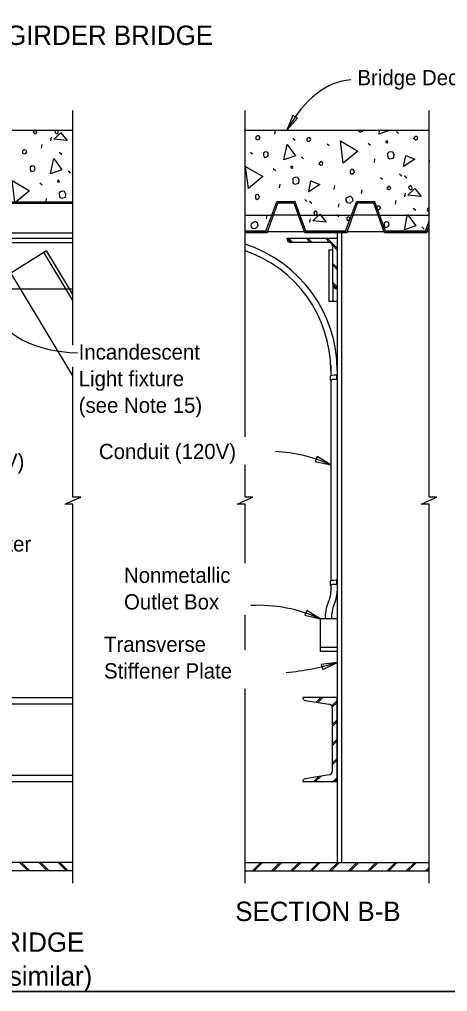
# Model space of a CAD drawing. Extents: x 0 to 30.8, y 0 to 21.2.
# Drawn here: x 8.22 to 12.47, y 0 to 9.63 of the extents above; entities that cross this region are included whole.
import ezdxf

# ---------------------------------------------------------------- set-up
doc = ezdxf.new("R2010")
doc.units = 0
for name, color, linetype in [('ActivePts-ConstElements', 7, 'Continuous'), ('Dimension', 7, 'Continuous'), ('Lighting', 7, 'Continuous'), ('Miscellaneous', 7, 'Continuous'), ('Miscellaneous1', 7, 'Continuous'), ('SteelGirder', 7, 'Continuous'), ('SteelGirder_h', 7, 'Continuous'), ('SupstrConc', 7, 'Continuous'), ('TextStructures', 7, 'Continuous')]:
    doc.layers.add(name, color=color, linetype=linetype)

msp = doc.modelspace()

# ---------------------------------------------------------------- linework, layer by layer
at = {"layer": 'ActivePts-ConstElements'}
msp.add_lwpolyline([(0, 0), (30.7879, 0), (30.7879, 19.4596), (0, 19.4596)], close=True, dxfattribs=at)
at = {"layer": 'Dimension'}
for points in [[(8.7519, 6.4065), (8.7519, 8.7314)], [(10.4598, 5.4959), (10.4598, 8.7314)], [(12.2847, 1.0713), (12.2847, 4.831), (12.2072, 4.831), (12.2847, 4.8647), (12.3622, 4.8985), (12.2847, 4.8985), (12.2847, 8.7314)], [(8.7519, 1.0713), (8.7519, 4.831), (8.6744, 4.831), (8.7519, 4.8647), (8.8294, 4.8985), (8.7519, 4.8985), (8.7519, 6.1908)], [(10.4598, 4.244), (10.4598, 4.831), (10.3823, 4.831), (10.4598, 4.8647), (10.5373, 4.8985), (10.4598, 4.8985), (10.4598, 5.2178)], [(10.4598, 3.3853), (10.4598, 3.7314)], [(10.4598, 1.0713), (10.4598, 2.9979)]]:
    msp.add_lwpolyline(points, dxfattribs=at)
for points in [[(10.8735, 8.5353), (10.9781, 8.6542), (10.9331, 8.682)], [(11.31, 5.2178), (11.176, 5.3023), (11.1557, 5.2534)], [(11.2058, 3.6925), (11.0718, 3.777), (11.0514, 3.7281)], [(11.3725, 3.2613), (11.2156, 3.2395), (11.2315, 3.189)]]:
    msp.add_lwpolyline(points, close=True, dxfattribs=at)
for centre, radius, start, end in [((10.6912, 3.8596), 1.4925, 65.50737, 87.36586), ((10.587, 2.3343), 1.4925, 65.50737, 92.69977), ((10.6816, 5.4517), 2.2968, 274.66721, 287.50633)]:
    msp.add_arc(centre, radius, start, end, dxfattribs=at)
for centre, major_axis, ratio, start_param, end_param in [((11.6186, 6.6665), (0.1111, -2.3674), 0.464296, 3.141604, 3.781059), ((9.2695, 7.2066), (1.3013, 0.4369), 0.58496, 3.141593, 4.152777)]:
    msp.add_ellipse(centre, major_axis=major_axis, ratio=ratio, start_param=start_param, end_param=end_param, dxfattribs=at)
at = {"layer": 'Lighting'}
for p, q in [((11.31, 6.2072), (11.31, 6.1026)), ((11.31, 6.059), (11.31, 4.0705)), ((11.31, 4.0268), (11.31, 3.9651)), ((11.3725, 3.6925), (11.2058, 3.6925)), ((11.2058, 3.6925), (11.2058, 3.3691)), ((11.2579, 3.6925), (11.2579, 3.7429)), ((11.3204, 3.6925), (11.3204, 3.7429)), ((11.3725, 3.4095), (11.2058, 3.4095)), ((11.3725, 3.3691), (11.2058, 3.3691))]:
    msp.add_line(p, q, dxfattribs=at)
for centre, radius, start, end in [((10.06, 6.1551), 1.3125, 0.00119, 72.26682), ((10.06, 6.1551), 1.25, 0, 71.34833), ((11.06, 3.9651), 0.25, 333.61151, 0), ((11.06, 3.9651), 0.3125, 333.61151, 0.00004), ((11.5079, 3.7429), 0.25, 153.61151, 179.99999), ((11.5079, 3.7429), 0.1875, 153.61151, 179.99999)]:
    msp.add_arc(centre, radius, start, end, dxfattribs=at)
at = {"layer": 'Miscellaneous'}
for p, q in [((10.7561, 8.4962), (10.7616, 8.5339)), ((11.96, 8.5237), (11.981, 8.5034)), ((8.4407, 8.3567), (8.4461, 8.3944)), ((8.5323, 8.4304), (8.5383, 8.4657)), ((10.932, 8.4579), (10.9578, 8.4389)), ((11.2732, 8.4018), (11.2935, 8.3839)), ((11.6806, 8.4074), (11.704, 8.3878)), ((8.6166, 8.3184), (8.6424, 8.2994)), ((10.5141, 8.3175), (10.5338, 8.302)), ((11.0183, 8.2714), (11.0392, 8.2511)), ((11.742, 8.2168), (11.7481, 8.2521)), ((12.2844, 8.2017), (12.2899, 8.2394)), ((8.7028, 8.1319), (8.7238, 8.1116)), ((10.7388, 8.1551), (10.7622, 8.1355)), ((11.9926, 8.1028), (12.0135, 8.0825)), ((8.4234, 8.0156), (8.4468, 7.996)), ((10.8003, 7.9645), (10.8063, 7.9998)), ((11.8028, 8.0675), (11.8231, 8.0496)), ((12.0414, 8.0848), (12.0624, 8.0646)), ((11.3427, 7.9494), (11.3481, 7.987)), ((11.615, 7.9085), (11.6204, 7.9461)), ((12.0431, 7.8756), (12.0492, 7.9109)), ((3.9317, 7.827), (8.7519, 7.827)), ((3.9359, 7.8114), (8.7519, 7.8114)), ((8.4852, 7.827), (8.4909, 7.8603)), ((10.6666, 7.5353), (10.7728, 7.827)), ((10.6775, 7.5197), (10.7837, 7.8114)), ((10.9561, 7.827), (10.7728, 7.827)), ((10.9452, 7.8114), (10.7837, 7.8114)), ((11.0514, 7.5197), (10.9452, 7.8114)), ((11.0623, 7.5353), (10.9561, 7.827)), ((11.0508, 7.8504), (11.0718, 7.8302)), ((11.0996, 7.8325), (11.1206, 7.8122)), ((11.3851, 7.7718), (11.3911, 7.8071)), ((11.457, 7.5353), (11.5632, 7.827)), ((11.468, 7.5197), (11.5742, 7.8114)), ((11.7465, 7.827), (11.5632, 7.827)), ((11.7356, 7.8114), (11.5742, 7.8114)), ((11.8418, 7.5197), (11.7356, 7.8114)), ((11.8527, 7.5353), (11.7465, 7.827)), ((11.9516, 7.8019), (11.957, 7.8396)), ((12.1275, 7.7636), (12.1532, 7.7447)), ((10.6732, 7.6561), (10.6787, 7.6938)), ((11.1013, 7.6233), (11.1074, 7.6586)), ((11.365, 7.7017), (11.3884, 7.6821)), ((12.2475, 7.5353), (12.2847, 7.6375)), ((3.2598, 7.5197), (8.7519, 7.5197)), ((10.6666, 7.5353), (10.4598, 7.5353)), ((10.6775, 7.5197), (10.4598, 7.5197)), ((11.468, 7.5197), (11.0514, 7.5197)), ((11.457, 7.5353), (11.0623, 7.5353)), ((12.2584, 7.5197), (11.8418, 7.5197)), ((12.2475, 7.5353), (11.8527, 7.5353)), ((12.2137, 7.5771), (12.2346, 7.5568)), ((12.2584, 7.5197), (12.2847, 7.5919)), ((10.9154, 7.4231), (10.8737, 7.4648)), ((10.9331, 7.4231), (10.8914, 7.4648)), ((11.1063, 7.4231), (11.0647, 7.4648)), ((11.124, 7.4231), (11.0823, 7.4648)), ((11.2997, 7.4207), (11.2556, 7.4648)), ((11.3725, 7.3655), (11.2732, 7.4648)), ((11.3725, 7.3478), (11.3282, 7.3921)), ((11.3725, 7.1746), (11.3308, 7.2162)), ((11.3725, 7.1569), (11.3308, 7.1986)), ((11.3725, 6.9837), (11.3308, 7.0253)), ((11.3725, 6.966), (11.3308, 7.0076)), ((11.0326, 2.907), (11.0382, 2.9127)), ((11.1652, 2.8664), (11.2115, 2.9127)), ((11.1804, 2.8639), (11.2291, 2.9127)), ((11.3178, 2.828), (11.3725, 2.8828)), ((11.3232, 2.8158), (11.3725, 2.8651)), ((11.3246, 2.644), (11.3725, 2.6919)), ((11.3246, 2.6263), (11.3725, 2.6742)), ((11.3246, 2.453), (11.3725, 2.5009)), ((11.3246, 2.4354), (11.3725, 2.4833)), ((11.3246, 2.2621), (11.3725, 2.31)), ((11.3246, 2.2444), (11.3725, 2.2924)), ((11.1418, 2.0793), (11.1925, 2.1301)), ((11.1595, 2.0793), (11.2137, 2.1335)), ((11.3327, 2.0793), (11.3725, 2.1191)), ((11.3504, 2.0793), (11.3725, 2.1014)), ((8.3064, 1.1941), (8.2231, 1.2774)), ((8.3241, 1.1941), (8.2408, 1.2774)), ((8.4973, 1.1941), (8.414, 1.2774)), ((8.515, 1.1941), (8.4317, 1.2774)), ((8.6882, 1.1941), (8.605, 1.2774)), ((8.7059, 1.1941), (8.6226, 1.2774)), ((10.5314, 1.1941), (10.6147, 1.2774)), ((10.5491, 1.1941), (10.6324, 1.2774)), ((10.7223, 1.1941), (10.8056, 1.2774)), ((10.74, 1.1941), (10.8233, 1.2774)), ((10.9133, 1.1941), (10.9965, 1.2774)), ((10.9309, 1.1941), (11.0142, 1.2774)), ((11.1042, 1.1941), (11.1875, 1.2774)), ((11.1219, 1.1941), (11.2051, 1.2774)), ((11.2951, 1.1941), (11.3784, 1.2774)), ((11.3128, 1.1941), (11.3961, 1.2774)), ((11.486, 1.1941), (11.5693, 1.2774)), ((11.5037, 1.1941), (11.587, 1.2774)), ((11.6769, 1.1941), (11.7602, 1.2774)), ((11.6946, 1.1941), (11.7779, 1.2774)), ((11.8679, 1.1941), (11.9511, 1.2774)), ((11.8855, 1.1941), (11.9688, 1.2774)), ((12.0588, 1.1941), (12.1421, 1.2774)), ((12.0765, 1.1941), (12.1597, 1.2774)), ((12.2497, 1.1941), (12.2847, 1.2291)), ((12.2674, 1.1941), (12.2847, 1.2114))]:
    msp.add_line(p, q, dxfattribs=at)
for points in [[(8.3561, 8.5178), (8.3703, 8.5035), (8.3855, 8.5049), (8.3932, 8.5148), (8.3919, 8.5196), (8.3832, 8.5328), (8.3768, 8.5353)], [(8.3699, 8.5353), (8.3638, 8.5276), (8.3561, 8.5178)], [(8.5617, 8.446), (8.6322, 8.5115), (8.6947, 8.4325), (8.5617, 8.446)], [(8.5821, 8.5353), (8.5796, 8.5337), (8.5713, 8.5263), (8.5752, 8.5118)], [(8.5752, 8.5118), (8.585, 8.504), (8.5984, 8.5025), (8.6067, 8.5099), (8.6065, 8.5202), (8.6009, 8.5316), (8.5981, 8.5353)], [(10.5674, 8.4663), (10.5671, 8.4481), (10.5849, 8.4399), (10.5987, 8.4462), (10.61, 8.4622), (10.6019, 8.473), (10.5951, 8.4789), (10.5842, 8.4812), (10.5793, 8.4799), (10.5674, 8.4663)], [(11.5846, 8.5353), (11.5938, 8.5188), (11.6114, 8.5209), (11.6228, 8.5265), (11.6279, 8.5353)], [(11.7865, 8.4953), (11.795, 8.5353)], [(11.8978, 8.5353), (11.7865, 8.4953)], [(10.8447, 8.243), (10.8767, 8.3939), (10.958, 8.2837), (10.8447, 8.243)], [(11.0738, 8.4312), (11.0799, 8.4276), (11.0957, 8.4267), (11.1082, 8.4378), (11.1111, 8.4464), (11.1024, 8.4596), (11.0818, 8.4592), (11.0734, 8.4518), (11.0712, 8.4408), (11.0738, 8.4312)], [(11.4335, 8.2092), (11.4055, 8.4295), (11.5776, 8.3281), (11.4335, 8.2092)], [(11.8545, 8.4152), (11.8758, 8.4131), (11.8732, 8.4228), (11.8651, 8.4336), (11.8543, 8.4255), (11.8545, 8.4152)], [(12.1347, 8.4515), (12.1531, 8.4408), (12.1675, 8.4447), (12.1727, 8.4642), (12.1537, 8.4772), (12.1453, 8.4698), (12.1363, 8.4648), (12.1347, 8.4515), (12.1334, 8.4563)], [(8.252, 8.3268), (8.2517, 8.3086), (8.2694, 8.3004), (8.2833, 8.3067), (8.2945, 8.3227), (8.2865, 8.3335), (8.2797, 8.3394), (8.2687, 8.3417), (8.2639, 8.3404), (8.252, 8.3268)], [(10.6435, 8.3081), (10.6421, 8.2844), (10.6521, 8.2664), (10.6696, 8.2685), (10.681, 8.2742), (10.6916, 8.2926), (10.6858, 8.3143), (10.6681, 8.3225), (10.656, 8.3192), (10.6435, 8.3081)], [(11.8733, 8.3064), (11.8747, 8.2627), (11.8955, 8.2528), (11.9075, 8.256), (11.9341, 8.2631), (11.9384, 8.2953), (11.924, 8.32), (11.9052, 8.3227), (11.8859, 8.3175), (11.8733, 8.3064)], [(8.5293, 8.1035), (8.5613, 8.2544), (8.6426, 8.1442), (8.5293, 8.1035)], [(11.1929, 8.1991), (11.2113, 8.1885), (11.2258, 8.1924), (11.2309, 8.2119), (11.2119, 8.2249), (11.2035, 8.2175), (11.1945, 8.2125), (11.1929, 8.1991), (11.1916, 8.2039)], [(12.0319, 8.178), (12.055, 8.2852), (12.1423, 8.249), (12.0319, 8.178)], [(8.328, 8.1686), (8.3266, 8.1449), (8.3366, 8.1269), (8.3542, 8.129), (8.3656, 8.1347), (8.3762, 8.1531), (8.3704, 8.1748), (8.3527, 8.183), (8.3406, 8.1797), (8.328, 8.1686)], [(10.4917, 7.9569), (10.4638, 8.1771), (10.6359, 8.0757), (10.4917, 7.9569)], [(10.9127, 8.1629), (10.934, 8.1608), (10.9314, 8.1705), (10.9234, 8.1812), (10.9126, 8.1732), (10.9127, 8.1629)], [(11.5033, 8.1322), (11.503, 8.114), (11.5196, 8.1003), (11.5352, 8.1097), (11.5454, 8.1201), (11.5421, 8.1322), (11.5328, 8.1478), (11.5163, 8.1512), (11.5038, 8.1401), (11.5033, 8.1322)], [(8.1751, 7.827), (8.1483, 8.0376), (8.3204, 7.9362), (8.188, 7.827)], [(8.5973, 8.0234), (8.6186, 8.0213), (8.616, 8.031), (8.6079, 8.0417), (8.5971, 8.0337), (8.5973, 8.0234)], [(10.9316, 8.054), (10.9329, 8.0104), (10.9537, 8.0004), (10.9658, 8.0037), (10.9923, 8.0108), (10.9966, 8.043), (10.9823, 8.0676), (10.9634, 8.0703), (10.9441, 8.0651), (10.9316, 8.054)], [(11.0902, 7.9257), (11.1132, 8.0328), (11.2006, 7.9967), (11.0902, 7.9257)], [(8.6161, 7.9145), (8.6175, 7.8709), (8.6383, 7.8609), (8.6503, 7.8642), (8.6769, 7.8713), (8.6812, 7.9035), (8.6668, 7.9281), (8.648, 7.9308), (8.6287, 7.9256), (8.6161, 7.9145)], [(11.867, 7.963), (11.8812, 7.9487), (11.8963, 7.9502), (11.904, 7.96), (11.9027, 7.9648), (11.894, 7.978), (11.8824, 7.9827), (11.8747, 7.9729), (11.867, 7.963)], [(12.0726, 7.8913), (12.143, 7.9568), (12.2056, 7.8778), (12.0726, 7.8913)], [(12.086, 7.957), (12.0958, 7.9493), (12.1092, 7.9477), (12.1176, 7.9551), (12.1174, 7.9654), (12.1117, 7.9768), (12.1037, 7.9876), (12.0905, 7.9789), (12.0821, 7.9715), (12.086, 7.957)], [(10.5615, 7.8798), (10.5612, 7.8616), (10.5778, 7.8479), (10.5934, 7.8573), (10.6036, 7.8678), (10.6003, 7.8799), (10.591, 7.8955), (10.5746, 7.8988), (10.562, 7.8877), (10.5615, 7.8798)], [(11.4573, 7.8403), (11.471, 7.8181), (11.5032, 7.8138), (11.5325, 7.8398), (11.526, 7.8639), (11.5088, 7.88), (11.496, 7.8792), (11.4756, 7.8685), (11.46, 7.8592), (11.4573, 7.8403)], [(11.1442, 7.7047), (11.1541, 7.6969), (11.1674, 7.6953), (11.1758, 7.7028), (11.1756, 7.7131), (11.17, 7.7245), (11.1619, 7.7353), (11.1487, 7.7266), (11.1403, 7.7191), (11.1442, 7.7047)], [(11.7753, 7.748), (11.7803, 7.7457), (11.7941, 7.752), (11.8054, 7.7679), (11.7973, 7.7787), (11.7905, 7.7847), (11.7796, 7.7869), (11.7748, 7.7856), (11.7655, 7.775)], [(12.2847, 7.7651), (12.2772, 7.765), (12.2689, 7.7575), (12.2666, 7.7466), (12.2692, 7.7369)], [(12.2692, 7.7369), (12.2753, 7.7334), (12.2847, 7.7328)], [(10.5155, 7.588), (10.5292, 7.5658), (10.5614, 7.5614), (10.5907, 7.5874), (10.5842, 7.6116), (10.567, 7.6276), (10.5543, 7.6268), (10.5338, 7.6162), (10.5182, 7.6068), (10.5155, 7.588)], [(11.1308, 7.6389), (11.2012, 7.7044), (11.2638, 7.6254), (11.1308, 7.6389)], [(11.4676, 7.6567), (11.4715, 7.6422), (11.4843, 7.6431), (11.4957, 7.6487), (11.5015, 7.6658), (11.4947, 7.6717), (11.4831, 7.6764), (11.4686, 7.6725), (11.4676, 7.6567)], [(11.8389, 7.6139), (11.8375, 7.5902), (11.8475, 7.5722), (11.865, 7.5743), (11.8765, 7.5799), (11.8871, 7.5983), (11.8812, 7.62), (11.8635, 7.6282), (11.8514, 7.625), (11.8389, 7.6139)], [(12.0401, 7.5487), (12.0721, 7.6996), (12.1534, 7.5894), (12.0401, 7.5487)]]:
    msp.add_lwpolyline(points, dxfattribs=at)
at = {"layer": 'Miscellaneous1'}
msp.add_lwpolyline([(0, 19.8), (30.8, 19.8), (30.8, 0), (0, 0)], close=True, dxfattribs=at)
at = {"layer": 'SteelGirder'}
for p, q in [((10.9879, 7.694), (10.741, 7.694)), ((11.7784, 7.694), (11.5314, 7.694)), ((11.0486, 7.5273), (10.6803, 7.5273)), ((11.3725, 7.5197), (11.3725, 1.2774)), ((11.4142, 7.5197), (11.4142, 1.2774)), ((11.839, 7.5273), (11.4708, 7.5273)), ((12.2847, 7.5273), (12.2612, 7.5273)), ((8.1297, 7.4647), (8.7519, 7.4647)), ((8.1297, 7.4231), (8.7519, 7.4231)), ((10.8725, 7.4648), (11.3725, 7.4648)), ((11.2892, 7.4231), (10.9142, 7.4231)), ((11.3725, 7.4648), (11.3725, 6.9648)), ((11.2891, 7.3502), (11.2891, 6.8404)), ((11.2891, 7.3502), (11.3309, 7.3502)), ((11.3308, 7.0064), (11.3308, 7.3814)), ((8.14, 6.9647), (8.7519, 6.9647)), ((8.7519, 6.1023), (8.2302, 6.9647)), ((8.7519, 6.9075), (8.7173, 6.9647)), ((11.3308, 7.0064), (11.3308, 6.8404)), ((11.2891, 6.8404), (11.3726, 6.8404)), ((11.3048, 6.0996), (11.3048, 6.059)), ((11.3673, 6.1159), (11.3725, 6.1159)), ((11.3673, 6.1159), (11.3673, 6.0664)), ((11.3673, 6.0752), (11.3725, 6.0752)), ((11.3048, 4.0675), (11.3048, 4.0268)), ((11.3673, 4.0837), (11.3725, 4.0837)), ((11.3673, 4.0837), (11.3673, 4.0343)), ((11.3673, 4.0431), (11.3725, 4.0431)), ((3.9428, 2.9126), (8.7519, 2.9126)), ((11.3725, 2.9127), (11.0308, 2.9127)), ((11.3725, 2.0793), (11.3725, 2.9127)), ((3.9428, 2.8502), (8.7519, 2.8502)), ((11.0547, 2.8845), (11.2933, 2.8455)), ((11.3246, 2.8085), (11.3246, 2.1835)), ((3.9428, 2.1419), (8.7519, 2.1419)), ((11.2933, 2.1465), (11.0547, 2.1075)), ((3.9428, 2.0794), (8.7519, 2.0794)), ((11.0308, 2.0793), (11.3725, 2.0793)), ((8.7519, 1.2774), (7.9683, 1.2774)), ((10.4598, 1.2774), (12.2847, 1.2774)), ((8.7519, 1.1941), (3.7374, 1.1941)), ((10.4598, 1.1941), (12.2847, 1.1941))]:
    msp.add_line(p, q, dxfattribs=at)
for centre, radius, start, end in [((10.9142, 7.4648), 0.0417, 180, 270), ((11.2892, 7.3814), 0.0417, 0, 90), ((11.3725, 7.0064), 0.0417, 180, 270), ((11.0594, 2.9127), 0.0286, 180, 260.5), ((11.2871, 2.8085), 0.0375, 360, 80.5), ((11.2871, 2.1835), 0.0375, 279.5, 360), ((11.0594, 2.0793), 0.0286, 99.5, 180)]:
    msp.add_arc(centre, radius, start, end, dxfattribs=at)
for centre, ratio, start_param, end_param in [((11.3673, 6.0996), 0.119608, 1.570506, 3.140799), ((11.3673, 6.059), 0.119608, 1.570506, 3.552397), ((11.3725, 6.059), 0.111403, 1.571206, 3.141305), ((11.3673, 4.0675), 0.119608, 1.570506, 3.140799), ((11.3673, 4.0268), 0.119608, 1.570506, 3.552397), ((11.3725, 4.0268), 0.111403, 1.571206, 3.141305)]:
    msp.add_ellipse(centre, major_axis=(0.0625, 0), ratio=ratio, start_param=start_param, end_param=end_param, dxfattribs=at)
at = {"layer": 'SteelGirder_h'}
for p, q in [((10.4598, 7.694), (10.741, 7.694)), ((10.9879, 7.694), (11.5314, 7.694)), ((11.7784, 7.694), (12.2847, 7.694)), ((10.4598, 7.5273), (10.6803, 7.5273)), ((11.0486, 7.5273), (11.4708, 7.5273)), ((11.839, 7.5273), (12.2612, 7.5273)), ((8.4908, 7.339), (8.1369, 7.1189)), ((8.7173, 6.9647), (8.4922, 7.3368)), ((8.7519, 6.8473), (8.4655, 7.3207)), ((8.2302, 6.9647), (8.1356, 7.1211))]:
    msp.add_line(p, q, dxfattribs=at)
at = {"layer": 'SupstrConc'}
for p, q in [((0.2637, 8.5353), (8.7519, 8.5353)), ((10.4598, 8.5353), (12.2847, 8.5353))]:
    msp.add_line(p, q, dxfattribs=at)

# ---------------------------------------------------------------- texts
at = {"layer": 'Dimension'}
for s, height, p in [('Incandescent', 0.1512, (8.8086, 6.2623)), ('Light fixture', 0.1512, (8.8086, 5.9983)), ('(see Note 15)', 0.1512, (8.8086, 5.7343)), ('Conduit (120V)', 0.1512, (6.9094, 5.1785)), ('Mini Power Center', 0.1512, (6.6746, 4.3597)), ('Nonmetallic', 0.1512, (9.2582, 4.0497)), ('Outlet Box', 0.1512, (9.2582, 3.7857)), ('Transverse', 0.1512, (9.06, 3.3652)), ('Stiffener Plate', 0.1512, (9.06, 3.1012)), ('LIGHTING DETAILS FOR STEEL BOX GIRDER BRIDGE', 0.192, (2.2732, 0.3922)), ('(Cross Frame section shown, other Transverse Stiffener sections similar)', 0.192, (0.6534, 0.0562))]:
    msp.add_text(s, height=height, dxfattribs=at).set_placement(p)
at = {"layer": 'TextStructures'}
for s, height, p in [('LIGHTING DETAILS FOR CONCRETE BOX GIRDER BRIDGE', 0.192, (2.9236, 9.3811)), ('Bridge Deck', 0.1512, (11.5739, 8.9822)), ('Conduit (120V)', 0.1512, (9.0094, 5.2763)), ('SECTION B-B', 0.192, (10.3616, 0.6975))]:
    msp.add_text(s, height=height, dxfattribs=at).set_placement(p)

doc.saveas('drawing.dxf')
